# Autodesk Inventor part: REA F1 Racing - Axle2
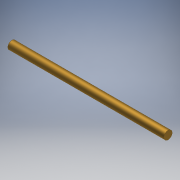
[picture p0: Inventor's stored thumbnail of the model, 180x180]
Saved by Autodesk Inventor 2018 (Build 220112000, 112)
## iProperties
Created: 2018-06
Part Number: REA F1 Racing - Axle2
Material: Generic
Document SubType Name: Modeling
Designer: Brett
Density: 1 g/cm^3
Appearance: Brass - Satin
Author: Brett
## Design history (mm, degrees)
sketch "Sketch1"
  geometry: C1 r 1.587 at (0, 0); 1 further point
  constraints: 1 centre point, 1 coincident
  dimensions: "d0" = 3.175 diameter of C1
extrude "Extrusion1" new body sketch "Sketch1" distance "d1" = 60; taper "d2" = 0 deg
body "Solid1"
